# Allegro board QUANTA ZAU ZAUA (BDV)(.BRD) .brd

Outline 219.8 x 128 mm; copper layers: TOP, SGND, IN1, IN2, SVCC, IN3, SGND1, BOTTOM. Coordinates in mm from the lower left corner of the outline.

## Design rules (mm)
constraint set DEFAULT: min track width 0.102
net group DFP-S4.5W4-T13B: nets USBP1+_C USBP1-_C
net group DFP-S4.5W4-TB: nets USBP1+_U14 USBP1-_U14
net group DFP-S6(5)W6.5(5.5)-T13B: nets M_B_CLK0 M_B_CLK0#
net group W7-T13B: nets 5447_CC1_CON 5447_CC2_CON
net group W20-T13B: nets +5V_HDMIC EDP_RCOMP
net group W60-T123B: nets +1.05V_LAN +1.05V_LAN_REGOUT
net group W80-T123B: nets +VCCPRTCPRIM_3P3 +VIN_BLIGHT
net group DFP-S3.5W4(3.5)-T13B: nets PEX_TSTCLK PEX_TSTCLK# VMA_CLK0 VMA_CLK0# VMA_CLK1 VMA_CLK1# VMA_WCK01 VMA_WCK01# VMA_WCK23 VMA_WCK23# VMA_WCK45 VMA_WCK45# VMA_WCK67 VMA_WCK67#
net group DFP-S4.5W4(3.5)-T13B: nets C_IN_CLK C_IN_CLK# C_IN_CLK#_R C_IN_CLK_R C_TX0_HDMI+ C_TX0_HDMI+_R C_TX0_HDMI- C_TX0_HDMI-_R C_TX1_HDMI+ C_TX1_HDMI+_R C_TX1_HDMI- C_TX1_HDMI-_R C_TX2_HDMI+ C_TX2_HDMI+_R C_TX2_HDMI- C_TX2_HDMI-_R CLK_PCIE_LANN CLK_PCIE_LANP CLK_PCIE_SSDN CLK_PCIE_SSDN_C CLK_PCIE_SSDP CLK_PCIE_SSDP_C CLK_PCIE_WLANN CLK_PCIE_WLANP CLK_VGA_N CLK_VGA_P IN_CLK IN_CLK# IN_CLK#_R IN_CLK_R IN_D0 IN_D0# IN_D0#_R IN_D0_R IN_D1 IN_D1# IN_D1#_R IN_D1_R IN_D2 IN_D2# IN_D2#_R IN_D2_R INT_EDP_AUXN INT_EDP_AUXN_C INT_EDP_AUXP INT_EDP_AUXP_C INT_EDP_TXN0 INT_EDP_TXN0_C INT_EDP_TXN1 INT_EDP_TXN1_C INT_EDP_TXN2 INT_EDP_TXN2_C INT_EDP_TXN3 INT_EDP_TXN3_C INT_EDP_TXP0 INT_EDP_TXP0_C INT_EDP_TXP1 INT_EDP_TXP1_C INT_EDP_TXP2 INT_EDP_TXP2_C INT_EDP_TXP3 INT_EDP_TXP3_C INT_HDMICLK+_OUT INT_HDMICLK-_OUT INT_HDMITX0N_OUT INT_HDMITX0P_OUT INT_HDMITX1N_OUT INT_HDMITX1P_OUT INT_HDMITX2N_OUT INT_HDMITX2P_OUT M_A_CLK0 M_A_CLK0# M_A_CLK1 M_A_CLK1# M_B_DQS0 M_B_DQS1 M_B_DQS2 M_B_DQS3 M_B_DQS4 M_B_DQS5 M_B_DQS6 M_B_DQS7 M_B_DQS#0 M_B_DQS#1 M_B_DQS#2 M_B_DQS#3 M_B_DQS#4 M_B_DQS#5 M_B_DQS#6 M_B_DQS#7 PCIE5_TXN PCIE5_TXP PCIE_RCOMPN PCIE_RCOMPP PCIE_RXN9_LAN PCIE_RXN10_WLAN PCIE_RXN13_SSD PCIE_RXN13_SSD_C PCIE_RXN14_SSD PCIE_RXN14_SSD_C PCIE_RXN15_SSD PCIE_RXN15_SSD_C PCIE_RXN16_SSD PCIE_RXN16_SSD_C PCIE_RXN_LAN_L PCIE_RXP9_LAN PCIE_RXP10_WLAN PCIE_RXP13_SSD PCIE_RXP13_SSD_C PCIE_RXP14_SSD PCIE_RXP14_SSD_C PCIE_RXP15_SSD PCIE_RXP15_SSD_C PCIE_RXP16_SSD PCIE_RXP16_SSD_C PCIE_RXP_LAN_L PCIE_TXN9_LAN PCIE_TXN10_WLAN PCIE_TXN13_SSD PCIE_TXN13_SSD_C PCIE_TXN14_SSD PCIE_TXN14_SSD_C PCIE_TXN15_SSD PCIE_TXN15_SSD_C PCIE_TXN16_SSD PCIE_TXN16_SSD_C PCIE_TXP9_LAN PCIE_TXP10_WLAN PCIE_TXP13_SSD PCIE_TXP13_SSD_C PCIE_TXP14_SSD PCIE_TXP14_SSD_C PCIE_TXP15_SSD PCIE_TXP15_SSD_C PCIE_TXP16_SSD PCIE_TXP16_SSD_C PEG_RXN5 PEG_RXN5_C PEG_RXN6 PEG_RXN6_C PEG_RXN7 PEG_RXN7_C PEG_RXN8 PEG_RXN8_C PEG_RXP5 PEG_RXP5_C PEG_RXP6 PEG_RXP6_C PEG_RXP7 PEG_RXP7_C PEG_RXP8 PEG_RXP8_C PEG_TXN5 PEG_TXN5_C PEG_TXN6 PEG_TXN6_C PEG_TXN7 PEG_TXN7_C PEG_TXN8 PEG_TXN8_C PEG_TXP5 PEG_TXP5_C PEG_TXP6 PEG_TXP6_C PEG_TXP7 PEG_TXP7_C PEG_TXP8 PEG_TXP8_C SATA_RXN0_C SATA_RXN0_IN SATA_RXN1A_C SATA_RXN1A_ODD SATA_RXN_OUT SATA_RXP0_C SATA_RXP0_IN SATA_RXP1A_C SATA_RXP1A_ODD SATA_RXP_OUT SATA_TXN0_C SATA_TXN0_CN SATA_TXN0_IN SATA_TXN1A_C SATA_TXN1A_ODD SATA_TXN_OUT SATA_TXP0_C SATA_TXP0_CN SATA_TXP0_IN SATA_TXP1A_C SATA_TXP1A_ODD SATA_TXP_OUT TYPEC_SBU1 TYPEC_SBU2 USB3_SS0RX+ USB3_SS0RX- USB3_SS0TX+ USB3_SS0TX- USB30_RX1+ USB30_RX1+_C USB30_RX1- USB30_RX1-_C USB30_RX2+ USB30_RX2- USB30_RX3+ USB30_RX3- USB30_RX+_TYPEC1 USB30_RX+_TYPEC2 USB30_RX-_TYPEC1 USB30_RX-_TYPEC2 USB30_TX1+ USB30_TX1+_C USB30_TX1+_C_R USB30_TX1- USB30_TX1-_C USB30_TX1-_C_R USB30_TX2+ USB30_TX2+_C USB30_TX2+_C_R USB30_TX2- USB30_TX2-_C USB30_TX2-_C_R USB30_TX3+ USB30_TX3- USB30_TX+_TYPEC1 USB30_TX+_TYPEC1_C USB30_TX+_TYPEC2 USB30_TX+_TYPEC2_C USB30_TX-_TYPEC1 USB30_TX-_TYPEC1_C USB30_TX-_TYPEC2 USB30_TX-_TYPEC2_C USBP1+_C_R USBP1+_C_R_N USBP1-_C_R USBP1-_C_R_N USBP2+ USBP2- USBP3+_TPC USBP3-_TPC USBP4+_DB USBP4-_DB USBP5+_CAM USBP5+_CAM_C USBP5-_CAM USBP5-_CAM_C USBP6+_CR USBP6-_CR USBP7+_FP USBP7-_FP USBP8+_TS USBP8-_TS USBP8_TS+_C USBP8_TS-_C USBP10+_BT USBP10-_BT USBP_TYPC+_C USBP_TYPC-_C
net group DFP-S4W4(3.5)-T13B: nets M_A_DQS0 M_A_DQS1 M_A_DQS2 M_A_DQS3 M_A_DQS4 M_A_DQS5 M_A_DQS6 M_A_DQS7 M_A_DQS#0 M_A_DQS#1 M_A_DQS#2 M_A_DQS#3 M_A_DQS#4 M_A_DQS#5 M_A_DQS#6 M_A_DQS#7
net group DFP-S11.5(11: nets MDI0+ MDI0+_1 MDI0- MDI0-_1 MDI1+ MDI1+_1 MDI1- MDI1-_1 MDI2+ MDI2+_1 MDI2- MDI2-_1 MDI3+ MDI3+_1 MDI3- MDI3-_1
net group GND: nets GND
net group W3.5-T13B: nets VCCGT_SENSE VCCSA_SENSE VCORE_SENSE VCORESS_SENSE VSSGT_SENSE VSSSA_SENSE
net group W3.5-T123B: nets ISEN1N_CORE ISEN1P_CORE ISEN2N_CORE ISEN2P_CORE
net group W4(3.5)-T13B: nets 3602_VRHOT CLK_24M_DEBUG CLK_24M_DEBUG_R CLK_PCI_EC CLK_PCI_EC_R CLK_PCI_LPC_R CPU_DRAMRST# DDR_DRAMRST# DGPU_HOLD_RST# DMIC_CLK DMIC_CLK_2 DMIC_CLK_2_R DMIC_CLK_L DMIC_CLK_L_C DMIC_DAT DMIC_DAT_2 DMIC_DAT_2_R DMIC_DAT_L DMIC_DAT_L_C DNBSWON# EC_PECI EC_PECR_R EC_PWROK EC_RCIN# GPU_PEX_RST_HOLD# H_PROCHOT# H_PROCHOT#_R HDA_BCLK_R HDA_RST#_R HDA_SDO_R HDA_SYNC_R HWPG IMVP_PWRGD INTRUDER# LAD1 LAD2 LAD3 LAN_XTAL1 LFRAME#_R LPC_LAD0 LPC_LAD1 LPC_LAD2 LPC_LAD3 LPC_LFRAME# M_A_DQ0 M_A_DQ1 M_A_DQ2 M_A_DQ3 M_A_DQ4 M_A_DQ5 M_A_DQ6 M_A_DQ7 M_A_DQ8 M_A_DQ9 M_A_DQ10 M_A_DQ11 M_A_DQ12 M_A_DQ13 M_A_DQ14 M_A_DQ15 M_A_DQ16 M_A_DQ17 M_A_DQ18 M_A_DQ19 M_A_DQ20 M_A_DQ21 M_A_DQ22 M_A_DQ23 M_A_DQ24 M_A_DQ25 M_A_DQ26 M_A_DQ27 M_A_DQ28 M_A_DQ29 M_A_DQ30 M_A_DQ31 M_A_DQ32 M_A_DQ33 M_A_DQ34 M_A_DQ35 M_A_DQ36 M_A_DQ37 M_A_DQ38 M_A_DQ39 M_A_DQ40 M_A_DQ41 M_A_DQ42 M_A_DQ43 M_A_DQ44 M_A_DQ45 M_A_DQ46 M_A_DQ47 M_A_DQ48 M_A_DQ49 M_A_DQ50 M_A_DQ51 M_A_DQ52 M_A_DQ53 M_A_DQ54 M_A_DQ55 M_A_DQ56 M_A_DQ57 M_A_DQ58 M_A_DQ59 M_A_DQ60 M_A_DQ61 M_A_DQ62 M_A_DQ63 M_B_ALERT# M_B_DQ0 M_B_DQ1 M_B_DQ2 M_B_DQ3 M_B_DQ4 M_B_DQ5 M_B_DQ6 M_B_DQ7 M_B_DQ8 M_B_DQ9 M_B_DQ10 M_B_DQ11 M_B_DQ12 M_B_DQ13 M_B_DQ14 M_B_DQ15 M_B_DQ16 M_B_DQ17 M_B_DQ18 M_B_DQ19 M_B_DQ20 M_B_DQ21 M_B_DQ22 M_B_DQ23 M_B_DQ24 M_B_DQ25 M_B_DQ26 M_B_DQ27 M_B_DQ28 M_B_DQ29 M_B_DQ30 M_B_DQ31 M_B_DQ32 M_B_DQ33 M_B_DQ34 M_B_DQ35 M_B_DQ36 M_B_DQ37 M_B_DQ38 M_B_DQ39 M_B_DQ40 M_B_DQ41 M_B_DQ42 M_B_DQ43 M_B_DQ44 M_B_DQ45 M_B_DQ46 M_B_DQ47 M_B_DQ48 M_B_DQ49 M_B_DQ50 M_B_DQ51 M_B_DQ52 M_B_DQ53 M_B_DQ54 M_B_DQ55 M_B_DQ56 M_B_DQ57 M_B_DQ58 M_B_DQ59 M_B_DQ60 M_B_DQ61 M_B_DQ62 M_B_DQ63 PCH_AZ_CODEC_BITCLK PCH_AZ_CODEC_RST# PCH_AZ_CODEC_SDIN0 PCH_AZ_CODEC_SDOUT PCH_AZ_CODEC_SYNC PCH_PWRBTN# PCH_SPI1_CLK PCH_SPI1_CLK_R PCH_SPI1_SI PCH_SPI1_SI_R PCH_SPI1_SO PCH_SPI1_SO_R PCH_SPI_CS0# PCH_SPI_CS0#_R PCH_SPI_IO2 PCH_SPI_IO3 PCIE_CLKREQ_LAN# PCIE_CLKREQ_SSD# PCIE_CLKREQ_VGA# PCIE_CLKREQ_WLAN# PCIE_WAKE# PEGX_RST# PEX_TERMP PLTRST# PROC_PWRGD PROCHOT_EC RSMRST# RTC_RST# RTC_X1 RTC_X2 SIO_RCIN# SPI_CLK_8M SPI_HOLD_IO3_ME SPI_SI_8M SPI_SO_8M SPI_TPM_CS# SPI_WP_IO2_ME SRTC_RST# SUSB# SUSC# SUSCLK_32K SUSCLK_32KHZ SYS_PEX_RST SYS_PEX_RST_MON# SYS_PWROK_R SYS_RESET# TESTMODE USB_OC0# USB_OC2# USBCOMP VCCST_PWRGD VCCST_PWRGD_R XCLK_BIASREF XDP_TCK0 XDP_TCK1 XDP_TDI_CPU XDP_TDO_CPU XDP_TMS_CPU XDP_TRST# XTAL1 XTAL2 XTAL24_IN XTAL24_IN_E3 XTAL24_IN_E3_R XTAL24_OUT XTAL24_OUT_C7 XTAL24_OUT_C7_R
net group W4(3.5)-T123B: nets 2ND_MBCLK 2ND_MBDATA 5V_HSMBCK 5V_HSMBDT 27M_XTAL_IN 27M_XTAL_OUT 3602_ALERT# 3602_CLK 3602_VDIO 8813VID BRIGHT CPU_THRMTRIP# DDCCLK_RIN DDCDATA_RIN DISP_ON GPUT_CLK_L GPUT_DATA_L H_CPU_SVIDART# H_CPU_SVIDCLK H_CPU_SVIDDAT HDMI_HPD HDMI_HPD_C HDMI_HPD_CON HDMI_MB_HPD_R HDMI_SCLK HDMI_SDATA HP_JD# ISEN1N_GT ISEN1N_SA ISEN1P_GT ISEN1P_SA PCH_BLON_C PCH_DISP_ON PCH_DPST_PWM PCH_LVDS_BLON PCH_MBCLK0_R PCH_MBDAT0_R PWM-VID SDVO_CLK SDVO_DATA SMB_ME1_CLK SMB_ME1_DAT SMB_RUN_CLK SMB_RUN_DAT SYS_SHDN# THRMTRIP# TP_I2C_CLK TP_I2C_DATA TP_SMB_CLK TP_SMB_DATA ULT_EDP_HPD ULT_EDP_HPD_R VGA_MBCLK VGA_MBDATA VGA_VCCSENSE VGA_VSSSENSE VR_SVID_ALERT#_VCORE
net group W4-T13B: nets CFG_RCOMP EDRAM_OPIO_RCOMP EMMC_RCOMP EOPIO_RCOMP PCH_OPI_RCOMP PROC_POPIRCOMP SD_1P8_RCOPM
net group W4-T123B: nets +TP_PWR_C
net group W5(4.5: nets FBA_CMD0 FBA_CMD1 FBA_CMD2 FBA_CMD3 FBA_CMD4 FBA_CMD5 FBA_CMD6 FBA_CMD7 FBA_CMD8 FBA_CMD9 FBA_CMD10 FBA_CMD11 FBA_CMD12 FBA_CMD13 FBA_CMD14 FBA_CMD15 FBA_CMD16 FBA_CMD17 FBA_CMD18 FBA_CMD19 FBA_CMD20 FBA_CMD21 FBA_CMD22 FBA_CMD23 FBA_CMD24 FBA_CMD25 FBA_CMD26 FBA_CMD27 FBA_CMD28 FBA_CMD29 FBA_CMD30 FBA_CMD31
net group W5-T123B: nets +FB_PLLAVDD +VCCDSW +VCCPRIM_3P3
net group W6-T123B: nets +PEX_PLL_HVDD +PEX_SVDD_3V3 PEX_PLLVDD
net group W6.5(5.5)-T13B: nets M_A_A0 M_A_A1 M_A_A2 M_A_A3 M_A_A4 M_A_A5 M_A_A6 M_A_A7 M_A_A8 M_A_A9 M_A_A10 M_A_A11 M_A_A12 M_A_A13 M_A_ACT# M_A_ALERT# M_A_BA#0 M_A_BA#1 M_A_BG#0 M_A_BG#1 M_A_CAS# M_A_CKE0 M_A_CKE1 M_A_CS#0 M_A_CS#1 M_A_ODT0_DIMM M_A_ODT1_DIMM M_A_PARITY M_A_RAS# M_A_WE# M_B_A0 M_B_A1 M_B_A2 M_B_A3 M_B_A4 M_B_A5 M_B_A6 M_B_A7 M_B_A8 M_B_A9 M_B_A10 M_B_A11 M_B_A12 M_B_A13 M_B_A14 M_B_A15 M_B_A16 M_B_ACT# M_B_BG#0 M_B_BG#1 M_B_BG#1_1 M_B_BS#0 M_B_BS#1 M_B_CKE0 M_B_CS#0 M_B_ODT0_MD M_B_PARITY
net group W6.5(6: nets FBA_DBI0 FBA_DBI1 FBA_DBI2 FBA_DBI3 FBA_DBI4 FBA_DBI5 FBA_DBI6 FBA_DBI7 FBA_EDC0 FBA_EDC1 FBA_EDC2 FBA_EDC3 FBA_EDC4 FBA_EDC5 FBA_EDC6 FBA_EDC7 VMA_DQ0 VMA_DQ1 VMA_DQ2 VMA_DQ3 VMA_DQ4 VMA_DQ5 VMA_DQ6 VMA_DQ7 VMA_DQ8 VMA_DQ9 VMA_DQ10 VMA_DQ11 VMA_DQ12 VMA_DQ13 VMA_DQ14 VMA_DQ15 VMA_DQ16 VMA_DQ17 VMA_DQ18 VMA_DQ19 VMA_DQ20 VMA_DQ21 VMA_DQ22 VMA_DQ23 VMA_DQ24 VMA_DQ25 VMA_DQ26 VMA_DQ27 VMA_DQ28 VMA_DQ29 VMA_DQ30 VMA_DQ31 VMA_DQ32 VMA_DQ33 VMA_DQ34 VMA_DQ35 VMA_DQ36 VMA_DQ37 VMA_DQ38 VMA_DQ39 VMA_DQ40 VMA_DQ41 VMA_DQ42 VMA_DQ43 VMA_DQ44 VMA_DQ45 VMA_DQ46 VMA_DQ47 VMA_DQ48 VMA_DQ49 VMA_DQ50 VMA_DQ51 VMA_DQ52 VMA_DQ53 VMA_DQ54 VMA_DQ55 VMA_DQ56 VMA_DQ57 VMA_DQ58 VMA_DQ59 VMA_DQ60 VMA_DQ61 VMA_DQ62 VMA_DQ63
net group W8-T123B: nets +3V_MAIN_1V8_AON +VCCATS_1P8 DVDD_IO
net group W10-T123B: nets +1.2VSUS +1.8V_DEEP_SUS +1V_S5 +3V +3V_EC +3V_LDO_EC +3V_S5 +3V_WLAN_P +3VPCU_EC +3VPCU_ECPLL +3VSPI +5VPCU +A3VPCU +G_SEN_PW +VCC_CORE +VCCHDA +VCCIO +VIN DCPRTC ECAGND ISOLATEB RSET
net group W11-T123B: nets +1V_VCCST
net group W12-T123B: nets +3V_GFX_+1V8_GFX_MAIN
net group W15-T13B: nets HP-L2 HP-L3 HP-R2 HP-R3 LINE1-L LINE1-R LINE1-VREFO-L LINE1-VREFO-R MIC2-VREFO SENSEA SM_RCOMP_0 SM_RCOMP_1 SM_RCOMP_2
net group W15-T123B: nets +1.8V +3V3AUX +3V_RTC +5V FB_CAL_PD_VDDQ NV_PLLVDD SP_PLLVDD
net group W20-T123B: nets +1.5V +1.8V_S5 +1.8V_SW +1V_SUS +2.5V_SUS +3V3_TPM +3V_RTC_1 +3V_RTC_2 +5V_FAN +5V_PVDD +5VA +AZA_VDD +SMDDR_VREF_DQ1_M1 +VCCPLL +VCCPRTC +VCCPSPI +VCCRTC_2 +VCCSTG +VDDQ +VDDQ_VTT +VDDQC +VREF_CA_CPU +VREF_CA_DIMM0 +VREFDQ_SB_M3 AVDD2 FB_CAL_TERM_GND FBA_VREFC_1 FBA_VREFC_2 PBA_PWR PBA_PWR_C PBA_PWR_R
net group W30-T123B: nets +5V_KB
net group W40-T13B: nets L_SPK+ L_SPK+_1 L_SPK- L_SPK-_1 R_SPK+ R_SPK+_1 R_SPK- R_SPK-_1 RING2 SLEEVE
net group W40-T123B: nets +3V_LAN +3V_PCH_ME +3VLCD_CON +3VLCD_CON_R +3VLCD_CON_R_C +601_VCC
net group W50-T123B: nets +PEX_IOVDDQ
net group W99-T123B: nets +1.03_GFX +1.35V_GFX +3V_SSD +5VODD +TYPEC_VBUS +TYPEC_VBUS_C +USBPWR0 +USBPWR1 +VCCGT_+VCORE +VCCSA +VGPU_CORE
nets with their own width: min track width 0.305; nets I2CA_SCL I2CA_SDA

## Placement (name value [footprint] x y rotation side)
C192  EV@0.22u/10V_2  [C0201]  103.31 42.48 180 bottom
C193  EV@0.22u/10V_2  [C0201]  103.31 43.22 180 bottom
C194  EV@0.22u/10V_2  [C0201]  102.14 41.31 180 bottom
C195  EV@0.22u/10V_2  [C0201]  102.14 42.07 180 bottom
C196  EV@0.22u/10V_2  [C0201]  102.14 43.5 180 bottom
C197  EV@0.22u/10V_2  [C0201]  102.14 44.23 180 bottom
C198  EV@0.22u/10V_2  [C0201]  102.27 46.37 180 bottom
C199  EV@0.22u/10V_2  [C0201]  102.27 45.63 180 bottom
C202  0.1u/16V_2  [C0201]  181.49 22.9 90 bottom
C203  0.1u/16V_2  [C0201]  180.78 22.9 90 bottom
C347  EV@10u/6.3V_4  [C0402]  118.3 118.22 90 bottom
C348  EV@10u/6.3V_4  [C0402]  120.2 118.73 0 bottom
C349  EV@4.7u/6.3V_4  [C0402_2]  120.2 117.46 0 bottom
C350  EV@4.7u/6.3V_4  [C0402_2]  116.77 117.97 180 bottom
C351  EV@1u/6.3V_4  [C0402]  107.5 102.98 0 top
C352  EV@1u/6.3V_4  [C0402]  107.5 100.7 0 top
C353  EV@1u/6.3V_4  [C0402]  109.41 102.86 0 top
C354  EV@1u/6.3V_4  [C0402]  111.45 108.59 90 top
C355  EV@47U/6.3V_6  [C0603]  107.5 120.64 180 bottom
C356  EV@4.7u/6.3V_4  [C0402_2]  113.09 119.24 180 bottom
C357  EV@4.7u/6.3V_4  [C0402_2]  105.6 104.51 180 top
C358  EV@0.22u/10V_2  [C0201]  100.9 121.14 90 top
C359  EV@22u/6.3V_6  [C0603]  107.5 119.11 180 bottom
C360  EV@4.7u/6.3V_4  [C0402_2]  121.98 117.84 0 top
C362  EV@1u/6.3V_4  [C0402]  110.63 110.86 270 top
C363  EV@10u/6.3V_4  [C0402]  120.2 116.32 0 bottom
C364  *EV@0.1u/16V_4  [C0402]  98.72 111.29 0 top
C365  EV@1u/6.3V_4  [C0402]  102.17 103.75 0 top
C366  EV@4.7u/6.3V_4  [C0402_2]  110.32 108.54 90 top
C367  EV@4.7u/6.3V_4  [C0402_2]  108.39 106.41 180 top
C368  EV@4.7u/6.3V_4  [C0402_2]  101.66 107.17 180 top
C369  EV@4.7u/6.3V_4  [C0402_2]  107.5 101.84 180 top
C370  EV@0.22u/10V_2  [C0201]  99.88 121.14 90 top
C371  EV@0.1u/16V_4  [C0402]  100.52 98.61 270 top
C372  EV@4.7u/6.3V_4  [C0402_2]  110.37 107.05 0 top
C373  EV@4.7u/6.3V_4  [C0402_2]  105.6 102.22 180 top
C374  EV@4.7u/6.3V_4  [C0402_2]  108.39 104.13 0 top
C375  EV@0.1u/16V_4  [C0402]  102.47 98.61 90 top
C376  EV@4.7u/6.3V_4  [C0402_2]  100.32 96.86 90 top
C377  EV@10u/6.3V_4  [C0402]  119.7 117.52 0 top
C378  EV@1u/6.3V_4  [C0402]  101.48 98.61 270 top
C379  EV@4.7u/6.3V_4  [C0402_2]  119.57 118.6 0 top
C380  EV@4.7u/6.3V_4  [C0402_2]  103.69 98.61 90 top
C381  EV@10u/6.3V_4  [C0402]  121.98 116.57 0 top
C382  EV@0.22u/10V_2  [C0201]  102.04 119.24 90 top
C383  EV@10u/6.3V_4  [C0402]  117.03 118.48 180 top
C384  EV@0.22u/10V_2  [C0201]  101.03 119.24 90 top
C385  EV@330u/2.5V_3528H1.9  [C3528]  87.44 107.43 90 bottom
C386  EV@22u/6.3V_6  [C0603]  105.09 98.84 90 top
C387  EV@47U/6.3V_6  [C0603]  116.65 120.89 90 top
C388  EV@10u/6.3V_4  [C0402]  110.3 119.11 0 bottom
C389  *EV@10u/6.3V_4  [C0402]  110.3 120.13 0 bottom
C391  *EV@10u/6.3V_4  [C0402]  107.12 117.84 180 bottom
C392  EV@4.7u/6.3V_4  [C0402_2]  90.1 101.97 90 top
C393  *EV@10u/6.3V_4  [C0402]  110.3 119.11 0 top
C394  EV@1u/6.3V_4  [C0402]  98.08 99.02 270 top
C395  EV@1u/6.3V_4  [C0402]  103.45 108.24 90 top
C396  EV@4.7u/6.3V_4  [C0402_2]  113.07 119.01 180 top
C397  EV@4.7u/6.3V_4  [C0402_2]  113.09 117.97 180 bottom
C398  EV@0.1u/16V_4  [C0402]  98.39 97.67 0 top
C399  EV@1u/6.3V_4  [C0402]  108.94 108.98 90 top
C400  EV@4.7u/6.3V_4  [C0402_2]  110.3 117.97 0 bottom
C401  EV@0.1u/16V_4  [C0402]  99.05 99.02 270 top
C402  EV@1u/6.3V_4  [C0402]  102.49 108.95 90 top
C403  EV@4.7u/6.3V_4  [C0402_2]  113.09 120.46 180 bottom
C406  EV@4.7u/6.3V_4  [C0402_2]  105.59 106.78 180 top
C407  EV@4.7u/6.3V_4  [C0402_2]  105.47 100.82 0 top
C408  EV@4.7u/6.3V_4  [C0402_2]  103.95 102.35 90 top
C409  EV@4.7u/6.3V_4  [C0402_2]  101.66 104.89 180 top
C410  EV@1u/6.3V_4  [C0402]  105.6 105.65 0 top
C411  EV@1u/6.3V_4  [C0402]  101.59 100.57 0 top
C412  EV@10u/6.3V_4  [C0402]  108.39 105.27 180 top
C413  EV@47U/6.3V_6  [C0603]  103.44 105.65 270 top
C414  *EV@47U/6.3V_6  [C0603]  107.15 109.3 0 top
C415  EV@10u/6.3V_4  [C0402]  105.6 103.36 0 top
C416  EV@47U/6.3V_6  [C0603]  108.77 110.73 180 top
C417  *EV@47U/6.3V_6  [C0603]  113.4 120.36 0 top
C418  EV@10u/6.3V_4  [C0402]  102.17 102.73 0 top
C419  EV@47U/6.3V_6  [C0603]  98.61 104.2 0 top
C420  *EV@47U/6.3V_6  [C0603]  116.9 120.51 180 bottom
C421  EV@10u/6.3V_4  [C0402]  103.57 100.72 0 top
C422  EV@47U/6.3V_6  [C0603]  108.01 119.75 90 top
C423  *EV@47U/6.3V_6  [C0603]  110.5 120.36 0 top
C424  EV@10u/6.3V_4  [C0402]  108.39 107.56 0 top
C425  EV@0.1u/16V_4  [C0402]  100.56 108.83 270 top
C426  EV@47U/6.3V_6  [C0603]  98.61 107.07 180 top
C427  *EV@47U/6.3V_6  [C0603]  98.61 105.62 180 top
C428  EV@10u/6.3V_4  [C0402]  101.52 108.7 90 top
C429  EV@4.7u/6.3V_4  [C0402_2]  89.85 108.44 0 top
C430  EV@10u/6.3V_4  [C0402]  102.17 101.71 180 top
C431  EV@4.7u/6.3V_4  [C0402_2]  99.48 108.67 270 top
C432  EV@10u/6.3V_4  [C0402]  101.66 106.03 0 top
C438  EV@1u/6.3V_4  [C0402]  121.88 93.59 90 top
C439  EV@1u/6.3V_4  [C0402]  110.3 104.89 180 top
C440  EV@1u/6.3V_4  [C0402]  123.12 93.59 90 top
C441  EV@1u/6.3V_4  [C0402]  139.38 105.02 90 top
C442  EV@1u/6.3V_4  [C0402]  136.21 105.02 90 top
C443  EV@10u/6.3V_4  [C0402]  109.41 100.44 180 top
C444  EV@10u/6.3V_4  [C0402]  110.31 103.83 180 top
C445  *EV@22U/6.3V_6  [C0603]  109.79 101.66 180 top
C446  *EV@22U/6.3V_6  [C0603]  121.09 102.73 90 bottom
C447  EV@1u/6.3V_4  [C0402]  109.41 99.43 180 top
C448  EV@10u/6.3V_4  [C0402]  110.3 105.9 180 top
C449  EV@1u/6.3V_4  [C0402]  108.39 98.41 180 top
C450  EV@1u/6.3V_4  [C0402]  107 99.3 90 top
C451  EV@22u/6.3V_6  [C0603]  119.44 102.73 90 bottom
C452  EV@0.1u/16V_4  [C0402]  102.17 118.86 180 bottom
C453  EV@22u/6.3V_4  [C0402_2]  106.61 97.57 90 top
C454  EV@0.1u/16V_4  [C0402]  111.19 102.86 180 top
C455  EV@0.1u/16V_4  [C0402]  110.17 98.41 180 top
C456  EV@0.1u/16V_4  [C0402]  120.2 114.54 180 bottom
C457  EV@0.1u/16V_4  [C0402]  99.86 100.7 0 top
C458  EV@22u/6.3V_4  [C0402_2]  98.13 100.54 180 top
C459  EV@0.1u/16V_4  [C0402]  100.01 102.98 0 top
C460  EV@0.1u/16V_4  [C0402]  100.01 101.97 0 top
C461  EV@10u/6.3V_4  [C0402]  98.61 102.48 270 top
C462  EV@47U/6.3V_6  [C0603]  89.98 106.54 270 top
C463  EV@12p/50V_4  [C0402]  102.07 89.37 180 bottom
C464  EV@12p/50V_4  [C0402]  100.29 89.37 0 bottom
C471  EV@22u/6.3V_6  [C0603]  142.17 116.22 270 top
C472  EV@22u/6.3V_6  [C0603]  136.71 95.74 0 top
C473  EV@22u/6.3V_6  [C0603]  136.71 79.74 0 bottom
C474  EV@22u/6.3V_6  [C0603]  123 118.45 0 bottom
C475  EV@22u/6.3V_6  [C0603]  126.81 104.51 0 top
C476  EV@22u/6.3V_6  [C0603]  120.46 96 90 bottom
C477  EV@1u/6.3V_4  [C0402]  128.59 106.03 180 top
C478  EV@1u/6.3V_4  [C0402]  138.95 86.89 0 top
C479  EV@1u/6.3V_4  [C0402]  127.47 92.65 270 top
C480  EV@1u/6.3V_4  [C0402]  132.08 113.06 270 top
C481  EV@1u/6.3V_4  [C0402]  134.94 115.18 180 top
C482  EV@1u/6.3V_4  [C0402]  134.68 108.83 90 top
C483  EV@1u/6.3V_4  [C0402]  127.57 86.73 270 top
C484  EV@10u/6.3V_4  [C0402]  139.38 109.08 270 top
C485  *EV@22U/6.3V_6  [C0603]  128.1 120 270 top
C486  *EV@22U/6.3V_6  [C0603]  123 116.95 0 bottom
C487  EV@22u/6.3V_6  [C0603]  129.98 120 180 bottom
C488  EV@22u/6.3V_6  [C0603]  136.71 97.65 0 top
C489  EV@22u/6.3V_6  [C0603]  123 115.43 0 bottom
C490  EV@22u/6.3V_6  [C0603]  121.98 96 90 bottom
C491  EV@1u/6.3V_4  [C0402]  139.89 93.59 0 top
C492  EV@1u/6.3V_4  [C0402]  131.51 116.83 90 top
C493  EV@1u/6.3V_4  [C0402]  134.68 117.21 180 top
C494  EV@1u/6.3V_4  [C0402]  130.62 92.19 270 top
C495  EV@1u/6.3V_4  [C0402]  130.36 108.44 0 top
C496  EV@1u/6.3V_4  [C0402]  130.74 86.73 90 top
C497  EV@1u/6.3V_4  [C0402]  130.01 79.97 180 bottom
C498  EV@1u/6.3V_4  [C0402]  138.23 112.69 0 top
C499  EV@1u/6.3V_4  [C0402]  131.81 79.97 0 bottom
C500  EV@10u/6.3V_4  [C0402]  137.35 117.46 180 top
C501  EV@10u/6.3V_4  [C0402]  136.46 90.28 0 top
C502  EV@10u/6.3V_4  [C0402]  128.59 90.92 180 top
C503  *EV@22U/6.3V_6  [C0603]  123.51 96 90 bottom
C504  *EV@22U/6.3V_6  [C0603]  134.05 79.74 0 bottom
C505  EV@820p/50V_4  [C0402]  133.92 98.03 180 top
C506  EV@820p/50V_4  [C0402]  132.65 103.11 0 top
C508  TPC@1u/10V_4  [C0402]  16.65 45.71 0 top
C509  100u/6.3V_12  [C1206]  21.04 53.8 0 bottom
C510  TPC@470p/50V_4  [C0402]  17.28 51.07 90 top
C511  TPC@0.1u/16V_4  [C0402]  20.13 56.93 0 bottom
C512  1u/6.3V_2  [C0201]  19.9 40.85 180 top
C513  *1.6p/50V_4  [C0402]  24.32 52.06 270 top
C514  0.1u/16V_4  [C0402]  18.25 57.01 0 bottom
C515  470p/50V_4  [C0402]  18.98 37.71 0 bottom
C516  0.1u/16V_4  [C0402]  20 42.02 0 bottom
C517  100u/6.3V_12  [C1206]  19.37 36.05 0 bottom
C518  *1.6p/50V_4  [C0402]  24.32 53.83 90 top
C519  0.1u/16V_4  [C0402]  25.46 56.88 0 top
C520  0.1u/16V_4  [C0402]  25.46 57.9 0 top
C521  *1.6p/50V_4  [C0402]  22.03 57.26 90 top
C522  *1.6p/50V_4  [C0402]  22.03 59.04 270 top
C523  *1.6p/50V_4  [C0402]  23.56 31.74 270 top
C524  1u/6.3V_2  [C0201]  203.39 22.59 90 bottom
C525  0.1u/16V_4  [C0402]  20.64 43.06 0 bottom
C526  *1.6p/50V_4  [C0402]  23.56 33.51 90 top
C527  470p/50V_4  [C0402]  210.3 23.46 270 bottom
C528  0.1u/16V_4  [C0402]  211.26 23.46 270 bottom
C529  *100u/6.3V_12  [C1206]  206.34 24.04 180 bottom
C530  0.1u/16V_4  [C0402]  25.08 36.94 0 top
C531  0.1u/16V_4  [C0402]  25.08 37.96 0 top
C532  *1.6p/50V_4  [C0402]  21.91 36.56 90 top
C533  *1.6p/50V_4  [C0402]  21.91 38.34 270 top
C536  0.1u/25V_4  [C0402]  65.8 107.22 180 top
C537  0.01u/50V_4  [C0402]  65.8 108.19 180 top
C542  4.7u/25V_6  [C0603]  66.53 114.46 90 bottom
C543  *0.047u/25V_4  [C0402]  60.41 105.04 270 bottom
C544  *0.047u/25V_4  [C0402]  61.43 105.04 270 bottom
C545  *22U/6.3V_6  [C0603]  61.56 98.61 0 top
C546  0.1u/16V_4  [C0402]  51.27 103.57 270 top
C547  10P/50V_4  [C0402]  51.14 109.05 90 top
C548  10P/50V_4  [C0402]  52.82 109.41 180 top
C550  *0.1u/16V_4  [C0402]  61.73 99.81 0 top
C552  0.1u/16V_4  [C0402]  55.31 103.52 90 bottom
C553  0.1u/16V_4  [C0402]  54.29 103.52 90 bottom
C554  0.1u/16V_4  [C0402]  53.27 103.52 90 bottom
C555  0.1u/16V_4  [C0402]  52.26 103.52 90 bottom
C556  0.1u/16V_4  [C0402]  62.06 108.65 180 top
C557  0.1u/16V_4  [C0402]  62.06 109.92 180 top
C558  33p/50V_4  [C0402]  55.92 106.23 90 top
C559  1u/6.3V_2  [C0201]  86.14 98.33 90 bottom
C560  0.01u/50V_4  [C0402]  80.38 95.62 90 bottom
C561  0.1u/16V_4  [C0402]  82.51 94.63 90 bottom
C562  10U/6.3V_4  [C0402]  83.48 94.63 90 bottom
C563  2.2u/6.3V_4  [C0402]  204.3 38.82 90 bottom
C564  10u/6.3V_4  [C0402_2]  203.21 38.75 270 bottom
C565  10u/6.3V_6  [C0603]  208.72 37.58 270 bottom
C566  1u/10V_6  [C0603]  208.82 39.64 180 bottom
C567  1u/10V_6  [C0603]  206.79 37.93 270 bottom
C568  0.1u/16V_4  [C0402]  199.83 37.07 270 bottom
C569  10u/6.3V_4  [C0402_2]  200.98 37.45 270 bottom
C572  10u/6.3V_4  [C0402_2]  210.12 37.32 90 bottom
C573  10u/6.3V_4  [C0402_2]  198.97 32.63 0 bottom
C574  10u/6.3V_4  [C0402_2]  207.98 30.03 0 top
C575  0.1u/16V_4  [C0402]  208.09 31.11 0 top
C576  10u/6.3V_4  [C0402_2]  208.09 32.19 0 top
C577  0.1u/16V_4  [C0402]  207.99 28.94 0 top
C578  10u/6.3V_4  [C0402_2]  203.37 26.38 90 bottom
C580  0.1u/16V_4  [C0402]  208.24 28.84 180 bottom
C581  10u/6.3V_4  [C0402_2]  206.51 29.58 270 top
C583  33p/50V_4  [C0402]  206.74 26.07 270 bottom
C584  0.1u/16V_4  [C0402]  202.29 26.4 90 bottom
C585  10u/6.3V_4  [C0402_2]  202.86 28.72 270 top
C586  *1000p/50V_4  [C0402]  210.63 36.69 180 top
C587  *22p/50V_4  [C0402]  204.52 26.58 270 bottom
C588  *0.1u/16V_4  [C0402]  210.63 33.64 180 top
C589  4.7u/6.3V_6  [C0603]  210.5 44.69 270 top
C590  100p/50V_4  [C0402]  213.35 42.43 0 top
C591  100p/50V_4  [C0402]  213.22 43.42 0 top
C592  100p/50V_4  [C0402]  213.29 47.76 180 top
C593  100p/50V_4  [C0402]  215.05 46.85 180 top
C594  4.7u/6.3V_6  [C0603]  212.53 44.61 180 top
C595  *1u/10V_4  [C0402]  211.8 30.31 270 bottom
C596  *0.1u/16V_4  [C0402]  203.13 30.06 0 top
C597  *10u/6.3V_6  [C0603]  213.17 29.07 270 top
C598  *10u/6.3V_6  [C0603]  197.83 35.39 180 bottom
C599  *0.1u/16V_4  [C0402]  198.44 36.59 0 bottom
C601  1000p/50V_4  [C0402]  119.65 24.12 270 bottom
C602  1000p/50V_4  [C0402]  118.25 24.12 270 bottom
C603  1000p/50V_4  [C0402]  116.85 24.12 270 bottom
C604  1000p/50V_4  [C0402]  115.45 24.12 270 bottom
C613  *10p/50V_4  [C0402]  23.3 63.61 270 top
C614  *10p/50V_4  [C0402]  23.3 65.39 90 top
C616  220p/50V_4  [C0402]  11.85 85.99 0 top
C618  HDMI_R@0.1u/16V_4  [C0402]  18.3 74.15 180 top
C619  HDMI_R@0.1u/16V_4  [C0402]  23.68 85.23 0 top
C628  HDMI_R@0.1u/16V_4  [C0402]  25.51 82.76 0 top
C631  0.1u/16V_4  [C0402]  41.08 105.57 0 bottom
C632  0.1u/16V_4  [C0402]  41.21 102.07 90 top
C633  0.1u/16V_4  [C0402]  40.24 102.04 90 top
C634  0.1u/16V_4  [C0402]  43.06 105.45 180 bottom
C635  1u/6.3V_4  [C0402]  49.19 106.97 270 top
C636  0.1u/16V_4  [C0402]  43.5 109.18 180 top
C637  0.1u/16V_4  [C0402]  50.18 100.6 180 top
C638  12p/50V_4  [C0402]  46.26 111.24 0 top
C639  12p/50V_4  [C0402]  44.49 111.24 180 top
C640  0.1u/16V_4  [C0402]  50.18 99.58 180 top
C641  0.1u/16V_4  [C0402]  43.5 101.71 0 top
C642  0.1u/16V_4  [C0402]  41.24 108.19 0 top
C643  *4.7u/6.3V_4  [C0402_2]  43.5 100.62 0 top
C644  *4.7u/6.3V_4  [C0402_2]  49.77 110.58 180 top
C645  0.01u/50V_4  [C0402]  28.15 101.79 90 top
C646  10p/3KV_1808  [CC1808]  21.4 112.51 234 bottom
C664  *0.1u/16V_4  [C0402]  212.23 23.46 270 bottom
C665  *22U/6.3V_6  [C0603]  210.5 25.69 270 bottom
C675  TPC@0.1u/25V_4  [C0402]  9.69 21.4 90 top
C676  TPC@0.1u/25V_4  [C0402]  10.7 21.4 90 top
C677  TPC@0.1u/16V_4  [C0402]  21.68 22.72 180 bottom
C680  TPC@0.1u/16V_4  [C0402]  17.59 25.51 90 bottom
C681  TPC@0.1u/16V_4  [C0402]  21.68 23.68 180 bottom
C682  TPC@0.1u/16V_4  [C0402]  21.68 21.75 180 bottom
C683  TPC@0.1u/16V_4  [C0402]  21.68 20.79 180 bottom
C684  TPC@0.1u/16V_4  [C0402]  18.6 25.51 90 bottom
C685  TPC@0.1u/16V_4  [C0402]  14.69 20.1 270 bottom
C686  TPC@0.1u/16V_4  [C0402]  15.66 20.1 270 bottom
C691  *TPC@390p/50V_4  [C0402]  12.99 19.26 90 top
C692  *TPC@390p/50V_4  [C0402]  11.06 13.45 270 top
C695  0.1u/16V_4  [C0402]  66.25 20.46 0 top
C696  10P/50V_4  [C0402]  75.68 19.44 180 top
C697  10P/50V_4  [C0402]  73.93 19.44 0 top
C698  *10p/50V_4  [C0402]  72.43 19.01 90 top
C699  *10p/50V_4  [C0402]  71.18 19.01 270 top
C706  220p/25V_2  [C0201]  156.32 18.78 270 top
C707  220p/25V_2  [C0201]  154.95 18.78 270 top
C708  220p/25V_2  [C0201]  153.35 18.78 270 top
C709  220p/25V_2  [C0201]  157.08 18.78 270 top
C711  220p/25V_2  [C0201]  157.92 18.78 270 top
C713  220p/25V_2  [C0201]  158.81 18.78 270 top
C714  220p/25V_2  [C0201]  159.98 18.78 270 top
C715  220p/25V_2  [C0201]  160.72 18.78 270 top
C716  220p/25V_2  [C0201]  151.93 18.78 270 top
C717  220p/25V_2  [C0201]  152.64 18.78 270 top
C718  220p/25V_2  [C0201]  154.24 18.78 270 top
C719  220p/25V_2  [C0201]  151.22 18.78 270 top
C720  220p/25V_2  [C0201]  168.57 18.91 180 top
C721  220p/25V_2  [C0201]  170.95 18.78 270 top
C722  220p/25V_2  [C0201]  167.68 18.78 270 top
C723  220p/25V_2  [C0201]  166.97 18.78 270 top
C724  220p/25V_2  [C0201]  171.66 18.78 270 top
C725  220p/25V_2  [C0201]  165.54 18.78 270 top
C726  220p/25V_2  [C0201]  170.09 18.91 180 top
C727  220p/25V_2  [C0201]  166.25 18.78 270 top
C728  220p/25V_2  [C0201]  161.48 18.78 270 top
C729  220p/25V_2  [C0201]  162.88 18.78 270 top
C730  220p/25V_2  [C0201]  163.76 18.78 270 top
C731  220p/25V_2  [C0201]  164.65 18.78 270 top
C732  220p/25V_2  [C0201]  148.04 18.78 270 top
C733  220p/25V_2  [C0201]  148.75 18.78 270 top
C734  *KBL@2.2u/10V_6  [C0603]  199.25 19.06 270 bottom
C736  KBL@4.7u/6.3V_4  [C0402_2]  202.14 20.97 270 bottom
C737  KBL@0.01u/50V_4  [C0402]  200.95 19.47 90 bottom
C740  TPM@10u/6.3V_6  [C0603]  129.6 24.27 180 top
C741  TPM@0.1u/10V_2  [C0201]  121.83 18.63 270 top
C742  TPM@0.1u/10V_2  [C0201]  129.55 22.39 90 top
C743  TPM@10u/6.3V_6  [C0603]  129.96 18.81 270 top
C744  TPM@0.1u/10V_2  [C0201]  121.12 18.63 270 top
C745  TPM@0.1u/10V_2  [C0201]  128.87 17.66 90 top
C749  *PBA@2.2u/16V_6  [C0603]  66.48 22.47 0 bottom
C750  *PBA@0.01u/50V_4  [C0402]  66.03 23.68 0 bottom
C752  PBA@4.7u/6.3V_4  [C0402_2]  60.77 22.87 270 bottom
C753  PBA@0.01u/50V_4  [C0402]  53.78 22.54 180 bottom
C770  *HDD@10u/6.3V_4  [C0402_2]  210.81 20.18 270 bottom
C771  HDD@10u/6.3V_4  [C0402_2]  209.54 20.18 270 bottom
C772  HDD@0.1u/16V_4  [C0402]  211.95 20.18 270 bottom
C773  ODD@0.01u/50V_4  [C0402]  132.65 21.4 90 bottom
C774  ODD@0.01u/50V_4  [C0402]  131.63 21.63 90 bottom
C775  *ODD@0.1u/16V_4  [C0402]  130.64 21.63 90 bottom
C776  *ODD@0.1u/16V_4  [C0402]  129.63 21.63 90 bottom
C777  ODD@10u/6.3V_6  [C0603]  128.41 21.83 270 bottom
C778  *ODD@100u/6.3V_12  [C1206]  126.58 22.21 270 bottom
C779  *ODD@15p/50V_4  [C0402]  133.67 21.68 270 bottom
C780  ODD@180p/50V_4  [C0402]  137.98 21.07 0 bottom
C781  ODD@0.01u/50V_4  [C0402]  133.7 17.51 270 top
C782  ODD@0.01u/50V_4  [C0402]  134.72 17.51 270 top
C783  ODD@0.01u/50V_4  [C0402]  135.75 17.51 270 top
C784  ODD@0.01u/50V_4  [C0402]  136.76 17.51 270 top
C785  SSD@0.1u/16V_2  [C0201]  38.92 4.43 270 top
C786  SSD@0.1u/16V_2  [C0201]  34.91 3.01 0 top
C788  SSD@0.22u/10V_4  [C0402]  36.67 6.27 270 top
C789  SSD@0.22u/10V_4  [C0402]  35.65 6.27 270 top
C790  SSD@0.22u/10V_4  [C0402]  34.66 6.46 270 top
C791  SSD@0.22u/10V_4  [C0402]  33.64 6.46 270 top
C792  SSD@0.22u/10V_4  [C0402]  31.63 6.46 270 top
C793  SSD@0.22u/10V_4  [C0402]  30.62 6.46 270 top
C794  SSD@0.22u/10V_4  [C0402]  28.64 6.46 270 top
C795  SSD@0.22u/10V_4  [C0402]  27.62 6.46 270 top
C800  0.1u/16V_2  [C0201]  193.5 29.96 90 bottom
C801  0.1u/16V_2  [C0201]  192.77 29.96 90 bottom
C802  10u/6.3V_4  [C0402_2]  194.45 29.91 270 bottom
C804  0.1u/16V_2  [C0201]  195.18 12.69 180 top
C805  10u/6.3V_4  [C0402_2]  197.12 11.54 270 bottom
C841  *0.1u/6.3V_2  [C0201]  39.08 116.45 90 bottom
C842  0.1u/16V_4  [C0402]  40.45 119.77 270 bottom
C843  256@0.1u/16V_4  [C0402]  198.57 31.31 0 bottom
C844  100p/50V_4  [C0402]  196.23 31.48 90 bottom
C845  10u/6.3V_4  [C0402_2]  210.12 35.42 270 bottom
C846  255@0.1u/16V_4  [C0402]  200.96 28.55 0 bottom
C847  HDMI_R@0.1u/10V_2  [C0201]  25.08 80.63 180 top
C848  HDMI_R@0.1u/10V_2  [C0201]  25.08 76.82 180 top
C849  HDMI_R@0.1u/10V_2  [C0201]  25.08 81.77 180 top
C850  HDMI_R@0.1u/10V_2  [C0201]  25.08 78.73 180 top
C851  HDMI_R@0.1u/10V_2  [C0201]  25.08 77.96 180 top
C852  HDMI_R@0.1u/10V_2  [C0201]  25.08 76.06 180 top
C853  HDMI_R@0.1u/10V_2  [C0201]  25.08 74.92 180 top
C854  HDMI_R@0.1u/10V_2  [C0201]  25.08 79.87 180 top
C1044  *0.1u/25V_6  [C0603]  24.34 39.2 180 top
C1189  0.1u/10V_2  [C0201]  181.54 24.24 180 top
C1190  0.1u/10V_2  [C0201]  179.69 24.28 0 top
C1208  180p/50V_4  [C0402]  201.89 22.52 0 top
C1210  180p/50V_4  [C0402]  202.3 21.55 180 top
C1675  0.1u/16V_4  [C0402]  50.23 103.52 90 bottom
C1676  0.1u/16V_4  [C0402]  51.24 103.52 90 bottom
C1677  0.1u/16V_4  [C0402]  49.21 103.52 90 bottom
C1678  0.1u/16V_4  [C0402]  48.19 103.52 90 bottom
C1679  HDMI_N@0.1u/10V_2  [C0201]  16.22 80.86 180 bottom
C1680  HDMI_N@0.1u/10V_2  [C0201]  16.22 76.67 180 bottom
C1681  HDMI_N@0.1u/10V_2  [C0201]  16.22 81.93 180 bottom
C1682  HDMI_N@0.1u/10V_2  [C0201]  16.22 78.83 180 bottom
C1683  HDMI_N@0.1u/10V_2  [C0201]  16.22 77.74 180 bottom
C1684  HDMI_N@0.1u/10V_2  [C0201]  16.22 75.83 180 bottom
C1685  HDMI_N@0.1u/10V_2  [C0201]  16.22 74.76 180 bottom
C1686  HDMI_N@0.1u/10V_2  [C0201]  16.22 79.89 180 bottom
C1687  HDMI_R@0.1u/16V_4  [C0402]  25.49 84.8 180 top
C1688  HDMI_R@0.1u/16V_4  [C0402]  25.46 85.81 180 top
C1689  HDMI_R@0.1u/16V_4  [C0402]  21.25 73.9 90 top
C1690  HDMI_R@0.1u/16V_4  [C0402]  25.46 86.8 180 top
C1691  HDMI_R@0.1u/16V_4  [C0402]  23.38 72.53 90 top
C1692  HDMI_R@0.1u/16V_4  [C0402]  22.31 73.47 90 top
C1693  HDMI_R@0.1u/16V_4  [C0402]  25.49 83.78 180 top
C2063  MD@1u/6.3V_4  [C0402]  30.55 101.78 90 top
C2064  MD@1u/6.3V_4  [C0402]  37.83 101.77 90 top
C2065  MD@1u/6.3V_4  [C0402]  36.79 101.77 90 top
C2066  MD@1u/6.3V_4  [C0402]  31.53 99.4 90 top
C2079  MD@10u/6.3V_4  [C0402_2]  28.71 99.65 0 top
C2080  MD@1u/6.3V_4  [C0402]  30.52 99.4 90 top
C2081  MD@1u/6.3V_4  [C0402]  27.9 94.86 0 top
C2082  MD@10u/6.3V_4  [C0402_2]  28.75 98.38 0 top
C2085  MD@2.2u/6.3V_4  [C0402]  37.44 97.22 270 top
C2086  MD@0.047u/25V_4  [C0402]  36.03 97.22 90 top
C2087  MD@1u/6.3V_4  [C0402]  27.9 97.22 0 top
C2088  MD@10u/6.3V_4  [C0402_2]  34.95 97.2 270 top
C2089  MD@10u/6.3V_4  [C0402_2]  40.6 97.17 270 top
C2090  MD@0.01u/50V_4  [C0402]  46.92 97.09 90 top
C2091  MD@1u/6.3V_4  [C0402]  45.91 97.1 270 top
C2092  MD@68p/50V_4  [C0402]  44.89 97.11 90 top
C2093  MD@1u/6.3V_4  [C0402]  43.9 97.11 270 top
C2094  MD@1u/6.3V_4  [C0402]  41.73 97.17 270 top
C2095  MD@68p/50V_4  [C0402]  42.74 97.16 90 top
C2097  MD@1u/6.3V_4  [C0402]  27.9 96.2 0 top
C2100  MD@10u/6.3V_4  [C0402_2]  29.68 84.71 0 top
C2101  MD@68p/50V_4  [C0402]  29.67 83.62 180 top
C2102  MD@1u/6.3V_4  [C0402]  50.05 79.08 90 top
C2103  MD@0.022u/25V_4  [C0402]  64.84 80.99 0 top
C2104  MD@2200p/50V_4  [C0402]  29.7 80.12 0 top
C2105  MD@0.1u/16V_4  [C0402]  29.7 79.08 180 top
C2106  1u/6.3V_4  [C0402]  55.84 90.18 180 top
C2107  1u/6.3V_4  [C0402]  64.86 59.27 90 top
C2108  22u/6.3V_6  [C0603]  104.1 76.35 270 top
C2109  22u/6.3V_6  [C0603]  102.68 76.36 270 top
C2110  1u/6.3V_4  [C0402]  50.4 88.02 180 top
C2111  22u/6.3V_6  [C0603]  105.52 75.42 270 top
C2112  10u/6.3V_6  [C0603]  103.08 74.28 0 top
C2113  10u/6.3V_6  [C0603]  87.92 66.56 180 top
C2115  10u/6.3V_6  [C0603]  100.93 74.53 90 top
C2119  1u/6.3V_4  [C0402]  91.53 81.82 270 top
C2120  1u/6.3V_4  [C0402]  91.04 84.11 90 top
C2121  1u/6.3V_4  [C0402]  97.62 79.84 90 top
C2122  10u/6.3V_6  [C0603]  86.1 82.98 180 bottom
C2124  MD@1u/6.3V_4  [C0402]  29.73 70.22 0 top
C2126  22u/6.3V_6  [C0603]  99.3 76.59 270 top
C2127  1u/6.3V_4  [C0402]  102.5 73.09 0 top
C2128  1u/6.3V_4  [C0402]  92.49 81.82 270 top
C2130  1u/6.3V_4  [C0402]  97.5 75.04 0 top
C2131  MD@1u/6.3V_4  [C0402]  29.73 69.07 0 top
C2132  1u/6.3V_4  [C0402]  50.4 86.93 180 top
C2133  MD@1u/6.3V_4  [C0402]  39.51 68.29 90 top
C2134  MD@1u/6.3V_4  [C0402]  40.55 68.28 90 top
C2135  MD@1u/6.3V_4  [C0402]  38.92 82.76 0 top
C2136  MD@2200p/50V_4  [C0402]  52.39 91.81 0 top
C2137  MD@1u/6.3V_4  [C0402]  52.74 67.09 180 top
C2138  MD@10u/6.3V_4  [C0402_2]  44.74 68.26 90 top
C2139  MD@1u/6.3V_4  [C0402]  41.56 68.28 90 top
C2140  1u/6.3V_4  [C0402]  86.63 86.07 315 top
C2141  22u/6.3V_6  [C0603]  100.77 77.24 90 top
C2142  1u/6.3V_4  [C0402]  87.23 84.24 90 top
C2143  1u/6.3V_4  [C0402]  93.58 85.46 180 bottom
C2144  10u/6.3V_4  [C0402_2]  87.26 67.88 180 top
C2145  10u/6.3V_4  [C0402_2]  96.28 76.94 0 top
C2146  MD@0.01u/50V_4  [C0402]  45.86 68.26 270 top
C2147  1u/6.3V_4  [C0402]  92.37 84.13 90 top
C2148  10u/6.3V_4  [C0402_2]  94.96 80.65 0 bottom
C2149  1u/6.3V_4  [C0402]  94.96 81.74 0 bottom
C2150  1u/6.3V_4  [C0402]  90.03 81.82 270 top
C2151  10u/6.3V_4  [C0402_2]  98.99 73.8 90 top
C2152  10u/6.3V_6  [C0603]  93.58 84.16 90 top
C2153  10u/6.3V_6  [C0603]  58.04 77.75 0 top
C2154  U42@22u/6.3V_6  [C0603]  85.08 69.02 180 top
C2155  10u/6.3V_6  [C0603]  89.85 84.36 90 top
C2156  U42@22u/6.3V_6  [C0603]  84.92 67.59 180 top
C2157  MD@1u/6.3V_4  [C0402]  55.71 77.56 180 top
C2158  MD@68p/50V_4  [C0402]  45.43 62.55 90 top
C2159  MD@1u/6.3V_4  [C0402]  44.28 62.55 270 top
C2160  MD@10u/6.3V_4  [C0402_2]  41.87 62.55 270 top
C2161  MD@1u/6.3V_4  [C0402]  40.73 62.55 270 top
C2162  MD@1u/6.3V_4  [C0402]  39.71 62.55 270 top
C2163  MD@0.047u/25V_4  [C0402]  38.57 62.55 90 top
C2164  MD@68p/50V_4  [C0402]  37.43 62.55 90 top
C2165  MD@0.047u/25V_4  [C0402]  36.28 62.55 90 top
C2166  MD@1u/6.3V_4  [C0402]  34.63 62.55 270 top
C2167  MD@0.1u/16V_4  [C0402]  33.49 62.55 90 top
C2168  22u/6.3V_6  [C0603]  88.43 84.34 90 top
C2169  U42@22u/6.3V_6  [C0603]  84.92 66.17 180 top
C2170  U42@22u/6.3V_6  [C0603]  85 64.75 180 top
C2171  1u/6.3V_4  [C0402]  40.8 82.76 180 top
C2172  U42@22u/6.3V_6  [C0603]  85 63.32 180 top
C2173  MD@3300p/50V_4  [C0402]  80.53 62.46 180 top
C2174  1u/6.3V_4  [C0402]  81.87 62.17 90 top
C2175  *22u/6.3V_6  [C0603]  115.58 50.56 270 top
C2176  22u/6.3V_6  [C0603]  89.67 58.04 270 top
C2177  1u/6.3V_4  [C0402]  96.51 56.96 225 top
C2178  1u/6.3V_4  [C0402]  92.7 58.79 90 top
C2179  10u/6.3V_4  [C0402_2]  96.3 59.42 270 top
C2180  *0.1u/16V_4  [C0402]  53.15 70.29 180 top
C2181  1u/6.3V_4  [C0402]  81.26 60.82 180 top
C2182  10u/6.3V_4  [C0402_2]  87.63 55.7 90 top
C2183  *22u/6.3V_6  [C0603]  108.9 67.3 90 top
C2184  22u/6.3V_6  [C0603]  110.37 67.3 90 top
C2185  22u/6.3V_6  [C0603]  114.69 58.46 90 top
C2186  22u/6.3V_6  [C0603]  113.22 58.41 90 top
C2187  10u/6.3V_6  [C0603]  48.6 66.58 0 top
C2188  10u/6.3V_4  [C0402_2]  81.74 59.46 270 top
C2189  10u/6.3V_4  [C0402_2]  84.97 55.76 90 top
C2190  22u/6.3V_6  [C0603]  86.57 58.03 270 top
C2191  MD@0.01u/50V_4  [C0402]  37.35 48.09 180 top
C2192  22u/6.3V_6  [C0603]  80.97 57.89 180 top
C2193  22u/6.3V_6  [C0603]  113.32 67.3 90 top
C2194  *22u/6.3V_6  [C0603]  113.22 61.12 270 top
C2195  *22u/6.3V_6  [C0603]  114.67 61.12 270 top
C2196  10u/6.3V_4  [C0402_2]  114.18 50.94 90 top
C2197  10u/6.3V_4  [C0402_2]  110.32 53.68 270 top
C2198  1u/6.3V_4  [C0402]  92.7 56.17 90 top
C2199  1u/6.3V_4  [C0402]  114.98 53.53 90 top
C2200  22u/6.3V_6  [C0603]  114.79 67.3 90 top
C2201  22u/6.3V_6  [C0603]  116.27 67.3 90 top
C2202  22u/6.3V_6  [C0603]  91.1 58 270 top
C2203  22u/6.3V_6  [C0603]  83.7 57.94 270 top
C2204  10u/6.3V_4  [C0402_2]  91.32 55.74 270 top
C2205  10u/6.3V_4  [C0402_2]  88.82 55.7 270 top
C2206  MD@1u/6.3V_4  [C0402]  29.68 52.65 0 top
C2207  10u/6.3V_4  [C0402_2]  92.82 61.33 90 top
C2208  10u/6.3V_4  [C0402_2]  90.13 55.7 90 top
C2209  MD@1u/6.3V_4  [C0402]  55.79 88.71 180 top
C2210  MD@68p/50V_4  [C0402]  29.68 51.51 180 top
C2211  10u/6.3V_4  [C0402_2]  81.55 55.32 270 top
C2212  1u/6.3V_4  [C0402]  65.87 59.27 90 top
C2213  1u/6.3V_4  [C0402]  91.2 53.94 270 top
C2214  10u/6.3V_4  [C0402_2]  113.9 53.53 270 top
C2215  10u/6.3V_4  [C0402_2]  112.96 50.91 90 top
C2216  1u/6.3V_4  [C0402]  93.69 58.79 90 top
C2217  22u/6.3V_6  [C0603]  111.9 67.3 90 top
C2218  10u/6.3V_4  [C0402_2]  88.91 53.94 270 top
C2219  22u/6.3V_6  [C0603]  88.25 58.05 270 top
C2220  22u/6.3V_6  [C0603]  85.15 58.02 270 top
C2221  10u/6.3V_4  [C0402_2]  83.86 53.95 90 top
C2222  10u/6.3V_4  [C0402_2]  87.49 53.96 270 top
C2223  10u/6.3V_4  [C0402_2]  86.27 54 270 top
C2224  10u/6.3V_4  [C0402_2]  85.08 54 90 top
C2225  10u/6.3V_4  [C0402_2]  90.1 53.94 270 top
C2226  10u/6.3V_4  [C0402_2]  86.19 55.76 90 top
C2227  10u/6.3V_4  [C0402_2]  83.63 55.69 90 top
C2228  MD@3.3p/50V_4  [C0402]  51.95 62.04 0 top
C2229  1u/6.3V_4  [C0402]  81.57 53.49 90 top
C2230  MD@0.01u/50V_4  [C0402]  39.41 48.07 0 top
C2231  22u/6.3V_6  [C0603]  113.17 55.76 270 top
C2232  10u/6.3V_4  [C0402_2]  112.71 53.53 270 top
C2233  10u/6.3V_4  [C0402_2]  111.52 53.53 270 top
C2234  1u/6.3V_4  [C0402]  97.42 58.71 90 top
C2235  1u/6.3V_4  [C0402]  93.69 55.74 90 top
C2236  MD@0.047u/25V_4  [C0402]  29.66 48.28 180 top
C2237  10u/6.3V_4  [C0402_2]  113.5 43.83 0 top
C2238  10u/6.3V_6  [C0603]  61.99 61.48 180 top
C2239  10u/6.3V_4  [C0402_2]  115.07 41.54 90 top
C2240  10u/6.3V_4  [C0402_2]  84.1 51.71 90 top
C2241  10u/6.3V_4  [C0402_2]  90.36 52.21 270 top
C2242  10u/6.3V_4  [C0402_2]  89.09 52.2 270 top
C2243  10u/6.3V_4  [C0402_2]  87.82 52.13 270 top
C2244  10u/6.3V_4  [C0402_2]  86.5 52.22 270 top
C2245  10u/6.3V_4  [C0402_2]  111.09 41.51 90 top
C2246  1u/6.3V_4  [C0402]  81.62 51.31 270 top
C2247  MD@3.3p/50V_4  [C0402]  29.66 47.2 180 top
C2248  10u/6.3V_4  [C0402_2]  82.92 51.54 90 top
C2249  1u/6.3V_4  [C0402]  63.84 59.27 90 top
C2250  0.022u/25V_4  [C0402]  53.78 57.31 270 top
C2251  MD@10u/6.3V_4  [C0402_2]  50.35 44.49 90 top
C2252  10u/6.3V_4  [C0402_2]  54.9 45.96 180 top
C2253  10u/6.3V_4  [C0402_2]  111.77 50.94 90 top
C2254  1u/6.3V_4  [C0402]  92.72 54.34 270 top
C2255  1u/6.3V_4  [C0402]  81.64 49.51 90 top
C2256  10u/6.3V_4  [C0402_2]  109.33 50.94 90 top
C2257  10u/6.3V_4  [C0402_2]  95.11 58.74 270 top
C2258  1u/6.3V_4  [C0402]  88.2 50.19 270 top
C2259  1u/6.3V_4  [C0402]  84.31 49.47 270 top
C2260  1u/6.3V_4  [C0402]  85.3 52.27 90 top
C2261  1u/6.3V_4  [C0402]  87.21 50.35 270 top
C2262  1u/6.3V_4  [C0402]  85.28 50.46 270 top
C2263  1u/6.3V_4  [C0402]  83.2 49.48 270 top
C2264  1u/6.3V_4  [C0402]  86.24 50.45 270 top
C2265  1u/6.3V_4  [C0402]  78.42 49.01 0 top
C2266  MD@0.01u/50V_4  [C0402]  29.68 44.92 180 top
C2267  10u/6.3V_4  [C0402_2]  63.66 52.31 90 top
C2268  0.1u/16V_4  [C0402]  85.48 48.56 90 top
C2269  10u/6.3V_4  [C0402_2]  64.91 52.31 90 top
C2270  1u/6.3V_4  [C0402]  94.98 56.17 270 top
C2271  10u/6.3V_4  [C0402_2]  109.84 43.29 270 top
C2272  10u/6.3V_4  [C0402_2]  113.78 41.54 90 top
C2273  10u/6.3V_4  [C0402_2]  112.05 43.27 270 top
C2274  1u/6.3V_4  [C0402]  82.22 47.74 270 top
C2275  1u/6.3V_4  [C0402]  84.14 47.53 0 top
C2276  1u/6.3V_4  [C0402]  86.45 48.62 90 top
C2277  10u/6.3V_4  [C0402_2]  110.58 50.94 90 top
C2278  10u/6.3V_4  [C0402_2]  66.15 52.31 90 top
C2279  10u/6.3V_6  [C0603]  52.61 68.39 180 top
C2280  1u/6.3V_4  [C0402]  82.96 46.09 180 top
C2281  *1u/6.3V_4  [C0402]  95.74 36.86 270 top
C2282  1u/6.3V_4  [C0402]  96.73 36.86 270 top
C2283  10u/6.3V_4  [C0402_2]  112.38 41.52 90 top
C2284  10u/6.3V_4  [C0402_2]  109.87 41.52 90 top
C2285  *22u/6.3V_6  [C0603]  117 50.56 270 top
C2286  1u/6.3V_4  [C0402]  96.15 38.23 180 top
C2287  10u/6.3V_4  [C0402_2]  116.51 41.94 90 top
C2288  0.1u/16V_4  [C0402]  50.25 53.38 0 top
C2289  2.2u/10V_6  [C0603]  50.15 58.25 270 top
C2290  22u/6.3V_6  [C0603]  114.59 55.76 270 top
C2291  0.1u/16V_4  [C0402]  97.7 36.88 270 top
C2292  1u/6.3V_4  [C0402]  99.71 44.61 45 top
C2293  10u/6.3V_6  [C0603]  62.29 52.31 90 top
C2294  10u/6.3V_6  [C0603]  57.34 54.6 90 top
C2295  1u/6.3V_4  [C0402]  64.53 42.71 0 top
C2296  0.1u/16V_4  [C0402]  101.31 40.7 180 top
C2297  2.2u/10V_6  [C0603]  50.15 48.37 90 top
C2298  1u/6.3V_4  [C0402]  59.55 52.16 90 top
C2299  1u/6.3V_4  [C0402]  98.46 39.64 90 top
C2300  0.1u/16V_4  [C0402]  51.73 50.23 180 top
C2301  0.1u/16V_4  [C0402]  64.53 41.74 180 top
C2302  10u/6.3V_4  [C0402_2]  61.45 59.32 270 top
C2305  10u/6.3V_4  [C0402_2]  62.7 59.27 270 top
C2306  1u/6.3V_4  [C0402]  61.43 81.39 90 top
C2307  22u/6.3V_6  [C0603]  100.09 37.32 90 top
C2308  1u/6.3V_4  [C0402]  101.46 44.78 270 top
C2309  1u/6.3V_4  [C0402]  102.47 44.78 270 top
C2310  10u/6.3V_6  [C0603]  58.91 54.55 90 top
C2311  MD@1u/6.3V_4  [C0402]  33.46 34.17 0 top
C2312  0.1u/16V_4  [C0402]  101 77.1 0 bottom
C2313  MD@1u/6.3V_4  [C0402]  46.49 33.6 90 top
C2314  MD@1u/6.3V_4  [C0402]  45.43 33.6 90 top
C2315  MD@10u/6.3V_4  [C0402_2]  41.87 33.6 90 top
C2316  MD@1u/6.3V_4  [C0402]  40.6 33.6 90 top
C2317  MD@1u/6.3V_4  [C0402]  39.46 33.6 90 top
C2318  10u/6.3V_6  [C0603]  60.79 52.31 90 top
C2319  MD@68p/50V_4  [C0402]  33.39 33.16 180 top
C2320  22u/6.3V_6  [C0603]  100.29 39.48 0 top
C2321  0.1u/16V_4  [C0402]  106.31 30.24 270 top
C2322  MD@1u/6.3V_4  [C0402]  34.07 31.94 0 top
C2334  1u/6.3V_4  [C0402]  53.01 39.58 0 top
C2335  0.1u/16V_4  [C0402]  101.81 26.25 270 top
C2336  *1000p/25V_2  [C0201]  105.19 25.06 90 top
C2337  *1000p/25V_2  [C0201]  105.93 25.06 90 top
C2339  1u/6.3V_4  [C0402]  55.79 35.93 180 top
C2342  0.1u/25V_4  [C0402]  56.43 31.94 270 top
C2343  2.2u/10V_6  [C0603]  55.22 31.79 270 top
C2344  1u/6.3V_4  [C0402]  49.26 28.74 90 top
C2345  1u/6.3V_4  [C0402]  50.45 28.77 90 top
C2346  1u/6.3V_4  [C0402]  50.35 31.08 180 top
C2347  *0.1u/16V_4  [C0402]  65.06 27.77 180 top
C2348  1u/6.3V_4  [C0402]  66.28 29.27 90 top
C2349  0.1u/16V_4  [C0402]  48.17 32.63 180 top
C2350  10u/6.3V_6  [C0603]  50.38 32.88 270 top
C2351  2.2u/10V_6  [C0603]  48.3 33.92 180 top
C2352  1u/6.3V_4  [C0402]  89.01 30.49 0 top
C2353  1u/6.3V_4  [C0402]  50.35 30.11 180 top
C2354  1u/6.3V_4  [C0402]  104.94 32.04 180 bottom
C2355  1u/6.3V_4  [C0402]  104.94 31.02 180 bottom
C2357  *1u/6.3V_4  [C0402]  86.04 29.7 90 top
C2358  1u/6.3V_4  [C0402]  85.02 28.03 180 top
C2359  1u/6.3V_4  [C0402]  101.69 36.13 0 top
C2360  *1u/6.3V_4  [C0402]  102.54 31.98 0 top
C2361  1u/6.3V_4  [C0402]  100.57 35.05 90 bottom
C2362  *1u/6.3V_4  [C0402]  100.57 33.28 90 bottom
C2363  0.1u/16V_2  [C0201]  62.83 30.29 180 top
C2369  0.1u/16V_2  [C0201]  64.88 32.5 270 top
C2374  180p/50V_4  [C0402]  180.78 19.42 90 top
C2418  1u/6.3V_4  [C0402]  56.25 26.83 180 top
C2419  1u/6.3V_4  [C0402]  56.22 25.69 0 top
C2420  1u/6.3V_4  [C0402]  52.08 26.81 270 top
C2531  47u/6.3V_8  [C0805]  81.32 90.59 270 bottom
C2532  47u/6.3V_8  [C0805]  79.31 90.59 270 bottom
C2533  47u/6.3V_8  [C0805]  74.94 83.15 90 bottom
C2534  47u/6.3V_8  [C0805]  77.66 86.02 90 bottom
C2535  0.1u/16V_2  [C0201]  68.11 83.7 90 bottom
C2536  47u/6.3V_8  [C0805]  77.33 90.59 270 bottom
C2537  47u/6.3V_8  [C0805]  79.64 86.02 90 bottom
C2538  22u/6.3V_6  [C0603]  85.8 81.55 180 bottom
C2539  22u/6.3V_6  [C0603]  92.58 81.62 180 bottom
C2540  22u/6.3V_6  [C0603]  89.35 81.61 0 bottom
C2541  1u/6.3V_4  [C0402]  97.83 82.04 90 bottom
C2542  1000p/50V_4  [C0402]  101 78.07 0 bottom
C2543  *0.1u/16V_2  [C0201]  100.65 75.22 180 bottom
C2544  22u/6.3V_6  [C0603]  85.8 80.08 180 bottom
C2545  22u/6.3V_6  [C0603]  92.58 80.09 180 bottom
C2546  22u/6.3V_6  [C0603]  89.34 80.09 180 bottom
C2559  1000p/50V_4  [C0402]  106.23 69.23 180 bottom
C2562  1u/6.3V_4  [C0402]  106.97 66 180 bottom
C2563  U22@33p/50V_4  [C0402]  101.28 62.7 180 bottom
C2564  U22@33p/50V_4  [C0402]  103.03 62.7 0 bottom
C2565  47u/6.3V_8  [C0805]  115.58 57.72 90 bottom
C2566  47u/6.3V_8  [C0805]  109 52.74 90 bottom
C2567  47u/6.3V_8  [C0805]  110.98 52.69 90 bottom
C2568  47u/6.3V_8  [C0805]  102.98 51.01 270 bottom
C2569  47u/6.3V_8  [C0805]  113.5 57.72 90 bottom
C2570  47u/6.3V_8  [C0805]  104.96 50.25 270 bottom
C2573  *10p/25V_2  [C0201]  64.81 47.87 0 bottom
C2574  0.1u/16V_2  [C0201]  103.31 45.35 180 bottom
C2575  *10p/25V_2  [C0201]  66.74 46.72 0 bottom
C2576  0.1u/16V_2  [C0201]  103.31 44.61 180 bottom
C2577  *10p/25V_2  [C0201]  66.74 45.99 0 bottom
C2578  *1u/6.3V_4  [C0402]  97.47 39.58 270 top
C2579  1u/6.3V_4  [C0402]  102.25 46.52 90 top
C2580  1u/6.3V_4  [C0402]  106.77 50.24 270 top
C2581  1u/6.3V_4  [C0402]  96.48 39.58 270 top
C2582  0.1u/16V_2  [C0201]  100.62 40.83 180 bottom
C2583  0.1u/16V_2  [C0201]  100.82 39.88 180 bottom
C2584  47u/6.3V_8  [C0805]  99.93 42.07 225 top
C2586  0.1u/16V_4  [C0402]  98.87 37.32 270 top
C2587  0.1u/16V_2  [C0201]  101.18 37.68 270 bottom
C2588  *0.1u/16V_2  [C0201]  66.48 29.25 0 bottom
C2589  U42@27p/50V_4  [C0402]  98.51 29.47 180 bottom
C2590  *10p/50V_4  [C0402]  66.43 28.22 180 bottom
C2591  U42@27p/50V_4  [C0402]  96.73 29.47 0 bottom
C2592  *10p/50V_4  [C0402]  66.45 26.88 0 bottom
C2593  *0.1u/16V_2  [C0201]  67.98 33.36 0 bottom
C2594  1u/6.3V_4  [C0402]  92.37 32.03 270 bottom
C2595  12p/50V_4  [C0402]  78.02 29.97 0 bottom
C2596  12p/50V_4  [C0402]  79.92 29.97 0 bottom
C2598  0.1u/16V_4  [C0402]  64.81 29.15 90 top
C2599  *1u/6.3V_2  [C0201]  92.04 37.68 180 top
C2601  0.1u/16V_4  [C0402]  67.14 23.68 0 top
C2602  1u/6.3V_4  [C0402]  83.07 31.51 180 bottom
C2603  1u/6.3V_4  [C0402]  66.66 24.73 180 top
C2606  *22p/50V_4  [C0402]  159.07 31.51 270 top
C2607  ODD@180p/50V_4  [C0402]  200.82 27.12 0 top
C2608  0.1u/16V_4  [C0402]  163.26 33.11 90 top
C2609  0.1u/16V_2  [C0201]  193.33 11.37 270 bottom
C2610  0.1u/16V_2  [C0201]  194.04 11.37 270 bottom
C2611  0.1u/16V_2  [C0201]  191.91 11.37 270 bottom
C2612  0.1u/16V_2  [C0201]  192.62 11.37 270 bottom
C2616  SSD@0.1u/16V_2  [C0201]  24.95 3.81 180 top
C6502  TPC@47u/6.3V_8  [C0805]  29.7 19.93 270 bottom
C6503  *TPC@47u/6.3V_8  [C0805]  30.29 14.16 180 bottom
C6504  TPC@22u/6.3V_6  [C0603]  27.37 17 0 top
C6505  TPC@10u/25V_8  [C0805]  21.5 14.57 270 bottom
C6544  TPC@0.1u/16V_4  [C0402]  13.94 23.76 270 bottom
C6545  TPC@0.1u/16V_4  [C0402]  12.98 23.76 270 bottom
C6546  TPC@0.1u/16V_4  [C0402]  15.33 23.79 270 bottom
C6547  TPC@0.1u/16V_4  [C0402]  29.78 16.95 180 bottom
C6548  TPC@22u/6.3V_6  [C0603]  27.7 14.03 90 bottom
C6549  TPC@22u/6.3V_6  [C0603]  28.26 20.05 270 top
C6554  EV@0.22u/10V_2  [C0201]  103.19 121.14 90 top
C6555  EV@0.22u/10V_2  [C0201]  103.31 119.24 90 top
C6556  EV@0.22u/10V_2  [C0201]  102.17 121.14 90 top
C6557  EV@0.22u/10V_2  [C0201]  104.33 119.24 90 top
C6560  *220p/50V_4  [C0402]  14.92 84.87 180 top
C6562  *10p/50V_4  [C0402]  179.26 23.35 180 top
C6563  180p/50V_4  [C0402]  182.56 31.48 0 top
C6564  10u/6.3V_6  [C0603]  199.32 10.83 0 top
C6565  0.1u/10V_2  [C0201]  200.67 25.72 90 top
C6566  0.1u/16V_4  [C0402]  201.99 17.75 180 top
C6568  180p/50V_4  [C0402]  194.88 11.16 180 top
C6569  0.1u/10V_2  [C0201]  192.67 12.25 0 top
C6570  0.1u/10V_2  [C0201]  192.67 11.49 0 top
C6571  1u/6.3V_4  [C0402]  181.04 22.34 0 top
C6572  180p/50V_4  [C0402]  183.32 29.96 270 top
C6573  0.1u/10V_2  [C0201]  184.77 31.61 270 top
C6574  0.1u/10V_2  [C0201]  186.6 31.48 90 top
C6575  0.1u/10V_2  [C0201]  191.4 31.36 0 top
C6577  0.1u/10V_2  [C0201]  180.66 18.05 270 top
C6578  0.1u/10V_2  [C0201]  181.42 18.05 270 top
C6580  180p/50V_4  [C0402]  196.1 31.76 90 top
C6581  TPC@150u/6.3V_3528H1.9  [C3528]  18.81 13.58 90 bottom
C6582  TPC@0.1u/25V_4  [C0402]  16.95 16.34 90 top
C6583  *TPC@0.1u/25V_4  [C0402]  15.96 6.29 0 top
C6584  TPC@0.1u/25V_4  [C0402]  24.98 12.99 90 top
C6586  HDD_R@0.01u/10V_2  [C0201]  212.28 19.93 270 top
C6587  HDD_R@0.01u/10V_2  [C0201]  211.01 19.93 270 top
C6588  HDD_R@0.01u/10V_2  [C0201]  210.25 19.93 270 top
C6589  HDD_R@0.01u/10V_2  [C0201]  208.98 19.93 270 top
C6590  HDD_N@0.01u/10V_2  [C0201]  212.41 12.11 90 top
C6591  HDD_N@0.01u/10V_2  [C0201]  211.14 12.11 90 top
C6592  HDD_N@0.01u/10V_2  [C0201]  210.37 12.11 90 top
C6593  HDD_N@0.01u/10V_2  [C0201]  209.23 12.11 90 top
C6594  HDD_R@0.01u/10V_2  [C0201]  212.41 12.56 270 top
C6595  HDD_R@0.01u/10V_2  [C0201]  211.14 12.56 270 top
C6596  HDD_R@0.01u/10V_2  [C0201]  210.37 12.56 270 top
C6597  HDD_R@0.01u/10V_2  [C0201]  209.23 12.56 270 top
C6598  HDD_R@0.1u/10V_2  [C0201]  215.23 17.13 270 top
C6599  HDD_R@0.1u/10V_2  [C0201]  214.51 17.13 270 top
C6600  HDD_R@0.1u/10V_2  [C0201]  207.96 12.94 0 top
C6601  HDD_R@0.1u/10V_2  [C0201]  215.94 17.13 270 top
C6602  HDD_R@0.1u/10V_2  [C0201]  207.96 13.7 0 top
C6603  GS@0.1u/10V_2  [C0201]  60.08 17.54 270 top
C6604  GS@33p/25V_2  [C0201]  52 19.44 180 top
C6605  GS@33p/25V_2  [C0201]  57.21 23.4 180 top
C6606  GS@0.1u/10V_2  [C0201]  48.35 16.09 0 top
C6607  HDD_R@10u/6.3V_4  [C0402_2]  207.45 11.54 90 top
C6608  GS@10u/6.3V_4  [C0402_2]  61.05 17.49 90 top
C6610  0.1u/16V_4  [C0402]  179.26 21.2 180 top
C6615  0.1u/10V_2  [C0201]  196.25 29.86 0 bottom
C6616  180p/50V_4  [C0402]  53.17 106.69 270 top
C6617  *15p/50V_4  [C0402]  90.89 28.04 90 bottom
C6624  0.1u/25V_4  [C0402]  63.1 104.18 0 top
C6625  1000p/50V_4  [C0402]  63.1 103.19 0 top
C20000  0.1u/16V_4  [C0402]  41.67 115.86 180 top
